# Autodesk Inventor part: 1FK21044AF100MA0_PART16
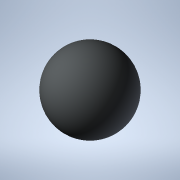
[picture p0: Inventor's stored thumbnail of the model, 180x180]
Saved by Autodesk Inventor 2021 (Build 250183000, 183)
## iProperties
Created: 2025-04
Part Number: 1FK21044AF100MA0_PART16
Material: Generic
Catalog Web Link: www.3dfindit.com
Description: -Servo synchronous motor
Document SubType Name: Modeling
Designer: psAdmin
Mass: 0.137258 g
Surface Area: 1.2868 cm^2
Volume: 0.137258 cm^3
Density: 1 g/cm^3
Appearance: PSOLRGB-212-217-219
Category: PARTsolutions
Title: 1FK21044AF100MA0_PART16
Author: Cadenas PARTsolutions
Comments: Servo synchronous motor
Sending System: PARTsolutions
Preprocessor: ST-DEVELOPER v19.3
PSOL_IDENT_0: {$CADENAS_DATA/23d-libs/siemens_ag/_cat_/ec/e4/1fk21044af100ma0.prj},216 {VTYP=3D},{NB=1FK21044AF100
PSOL_IDENT_1: MA0_PART16},{LINA=1FK21044AF100MA0_PART16},{NN=1FK21044AF100MA0_PART16},{NOPRJ=TRUE},{DATE=19.08.202
PSOL_IDENT_2: 5 14:01:05},{GEOMDATE=30.07.2025 02:01:01},{VERSION=},{LINEID=10},{WBVAR=},{WBNUMERIC=}  {NB=1FK2104
PSOL_IDENT_3: 4AF100MA0_PART16},{LINA=1FK21044AF100MA0_PART16},{KT=DUMMY},{PREVIEW=../../../_pool_/cb/72/p_d211_xx
PSOL_IDENT_4: _00434j.png},{DESCSHORT=SIMOTICS S-1FK2 HD, SINAMICS S210 3AC 400V-480V, 1.27 Nm, 3000 rpm},{DESCLON
PSOL_IDENT_5: G=SIMOTICS S-1FK2 HD servo motor M0=1.27 Nm; PN = 0.4 kW at nN=3000 rpm (380-480 V); PN = 0.2 kW at
PSOL_IDENT_6: nN=1500 rpm (200-240 V); with holding brake; degree of protection IP64; cylindrical shaft D19x40mm;
PSOL_IDENT_7: absolute encoder 22-bit + 12-bit multiturn (encoder AM22DQC); with OCC interface; plug size M17, rot
PSOL_IDENT_8: atable; SIMOTICS S-1FK2 servomotorfor a wide range of uses in industrial environments. SIMOTICS S‑1F
PSOL_IDENT_9: K2 servomotors are compact synchronous motors with a high dynamic performance that set themselves ap
PSOL_IDENT_10: art as a result of their high power density, degree of protection and overload capability. The motor
PSOL_IDENT_11: s are available in two variants: as High Dynamic variant (highest dynamic performance as a result of
PSOL_IDENT_12: the low intrinsic moment of inertia for applications demanding a high dynamic performance with low
PSOL_IDENT_13: moved masses) - and as Compact variant (precise and stable closed-loop control for medium up to larg
PSOL_IDENT_14: e moved masses as a result of a medium intrinsic moment of inertia). SIMOTICSS‑1FK2 servomotors full
PSOL_IDENT_15: y exploit their strengths in a system with the SINAMICSS210 frequency converter and simple connectio
PSOL_IDENT_16: n using the one cable connection (OCC). Advantages include the short control and positioning times,
PSOL_IDENT_17: fast and precise correction of disturbing quantities as well as stable control with a high dynamic p
PSOL_IDENT_18: erformance. The servo motors can be configured to address a wide range of requirements. For example
PSOL_IDENT_19: with and without holding brake, IP64 or IP65 degree of protection, singleturn or multiturn absolute
PSOL_IDENT_20: encoders - to name just a few. Further, the servomotors are available in different shaft heights ext
PSOL_IDENT_21: ending from 20 to 100. A shaft sealing ring is available to achieve an IP65 degree of protection and
PSOL_IDENT_22: for subsequent mounting at the motor or as spare part. SIMOTICS - the optimum motor for each and ev
PSOL_IDENT_23: ery motion control application.},{INTNO=195125043275},{SUPPLIERALTNO=1FK2104-4AF10-0MA0},{MANUID=1FK
PSOL_IDENT_24: 21044AF100MA0},{MANUNAME=Siemens},{MANUTYPEDESC=Synchronous motor 1FK2-HD 1.27 NM},{AAU732=SIMOTICS}
PSOL_IDENT_25: ,{AAO057=S-1FK2},{AAU734=SIMOTICS S-1FK2 HD servo motor M0=1.27 Nm; PN = 0.4 kW at nN=3000 rpm (380-
PSOL_IDENT_26: 480 V); PN = 0.2 kW at nN=1500 rpm (200-240 V); with holding brake; degree of protection IP64; cylin
PSOL_IDENT_27: drical shaft D19x40mm; absolute encoder 22-bit + 12-bit multiturn (encoder AM22DQC); with OCC interf
PSOL_IDENT_28: ace; plug size M17, rotatable;},{AAW338=Synchronous motor 1FK2-HD 1.27 NM},{AAO742=SIMOTICS},{AAO663=
PSOL_IDENT_29: 4042948694015},{NOCUPEROU=1},{PRICEQUANTITY=1},{QUANTITYMIN=1},{QUANTITYINT=1},{CTN=85015100},{COO=D
PSOL_IDENT_30: E},{AAO676=1FK2104-4AF10-0MA0},{AAO677=Siemens AG},{ORDERUNIT=C62},{CONTENTUNIT=C62}
NB: 1FK21044AF100MA0_PART16
NT: Servo synchronous motor
NBSYN: $MANUID._PART16
LINA: 1FK21044AF100MA0_PART16
CATALOG: SIEMENS
PREVIEW: ../../../_pool_/cb/72/p_d211_xx_00434j.png
DESCSHORT: SIMOTICS S-1FK2 HD, SINAMICS S210 3AC 400V-480V, 1.27 Nm, 3000 rpm
DESCLONG: SIMOTICS S-1FK2 HD servo motor M0=1.27 Nm; PN = 0.4 kW at nN=3000 rpm (380-480 V); PN = 0.2 kW at nN=1500 rpm (200-240 V); with holding brake; degree of protect
INTNO: 195125043275
SUPPLIERALTNO: 1FK2104-4AF10-0MA0
MANUID: 1FK21044AF100MA0
MANUNAME: Siemens
MANUTYPEDESC: Synchronous motor 1FK2-HD 1.27 NM
AAU732: SIMOTICS
AAO057: S-1FK2
AAU734: SIMOTICS S-1FK2 HD servo motor M0=1.27 Nm; PN = 0.4 kW at nN=3000 rpm (380-480 V); PN = 0.2 kW at nN=1500 rpm (200-240 V); with holding brake; degree of protect
AAW338: Synchronous motor 1FK2-HD 1.27 NM
AAO742: SIMOTICS
AAO663: 4042948694015.0
NOCUPEROU: 1
PRICEQUANTITY: 1
QUANTITYMIN: 1
QUANTITYINT: 1
CTN: 85015100
COO: DE
ARTICLENO: 1FK21044AF100MA0_PART16
BOMINFO: 1FK21044AF100MA0_PART16
CREATOR: CADENAS GmbH
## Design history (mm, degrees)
feature "2025_04_17_15_33_01_0673"
body "Solid1"
